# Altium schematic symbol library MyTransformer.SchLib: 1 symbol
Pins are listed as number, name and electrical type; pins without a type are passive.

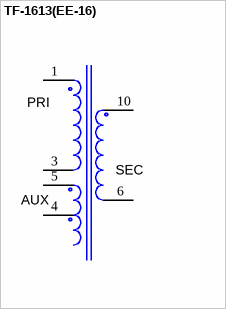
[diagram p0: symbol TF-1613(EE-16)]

## TF-1613(EE-16)
designator U?
Manufacturer: Taiwan Shulin Enterprise Co. Ltd.; SymbolVersion: 1.0; SymbolCreator: A0283112; CompType: Transformer; U/M: EA, IN, or GM
footprint PCBComponent_1
pins: 1, 3, 4, 5, 6, 10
